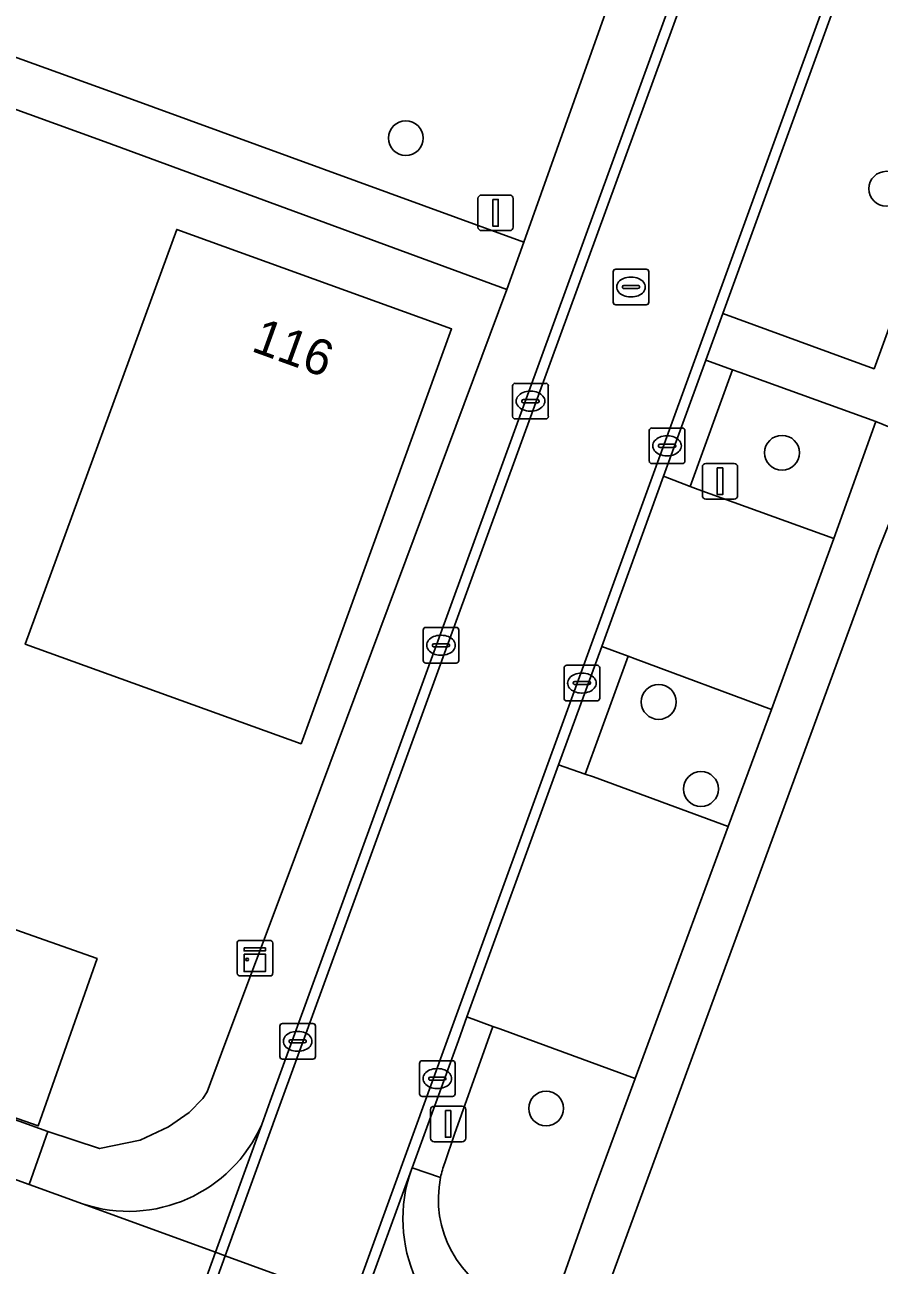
# Model space of a CAD drawing. Extents: x 155275 to 156265, y 382654 to 383635.
# Drawn here: x 155961.56 to 155985.53, y 382876.12 to 382910.94 of the extents above; entities that cross this region are included whole.
import ezdxf

# ---------------------------------------------------------------- set-up
doc = ezdxf.new("R2010")
doc.units = 0
for name, color, linetype in [('IMGEO_Boom', 7, 'Continuous'), ('IMGEO_Erf', 7, 'Continuous'), ('IMGEO_Groenvoorziening', 7, 'Continuous'), ('IMGEO_Kast', 7, 'Continuous'), ('IMGEO_Kolk', 7, 'Continuous'), ('IMGEO_Lichtmast', 7, 'Continuous'), ('IMGEO_Pand', 7, 'Continuous'), ('IMGEO_Pand_nummerreeks', 7, 'Continuous'), ('IMGEO_Parkeervlak_open', 7, 'Continuous'), ('IMGEO_Rijbaan_lokaal_gesloten', 7, 'Continuous'), ('IMGEO_Rijbaan_lokaal_open', 7, 'Continuous'), ('IMGEO_Rioolput', 7, 'Continuous'), ('IMGEO_Voetpad_open', 7, 'Continuous')]:
    doc.layers.add(name, color=color, linetype=linetype)

msp = doc.modelspace()

# ---------------------------------------------------------------- linework, layer by layer
at = {"layer": 'IMGEO_Boom'}
for centre in [(155972.247, 382907.764), (155985.731, 382906.343), (155982.803, 382898.931), (155979.343, 382891.936), (155980.529, 382889.492), (155976.184, 382880.524)]:
    msp.add_circle(centre, 0.489, dxfattribs=at)
at = {"layer": 'IMGEO_Erf'}
for points in [[(155975.085, 382903.519), (155963.808, 382907.656), (155935.757, 382917.844), (155923.739, 382922.208), (155888.788, 382934.902), (155887.843, 382935.242), (155879.927, 382913.581)], [(155882.198, 382908.814), (155888.809, 382906.56), (155914.272, 382897.319), (155926.717, 382892.835), (155943.231, 382886.789), (155948.645, 382884.835), (155950.836, 382890.892), (155956.798, 382888.735), (155954.606, 382882.673), (155954.644, 382882.601), (155962.207, 382879.881), (155963.654, 382879.4), (155964.795, 382879.631), (155965.592, 382880.01), (155966.17, 382880.408), (155966.548, 382880.807), (155966.671, 382880.994), (155967.174, 382882.325), (155968.914, 382886.988), (155975.085, 382903.519)], [(156049.271, 382876.469), (155986.733, 382899.275), (155985.513, 382896.209), (155977.474, 382874.314), (156011.194, 382862.059), (156017.047, 382859.976), (156014.804, 382853.502), (156014.672, 382853.55), (155989.659, 382862.664), (155989.671, 382862.757), (155975.249, 382867.763), (155964.586, 382839.123)]]:
    msp.add_lwpolyline(points, dxfattribs=at)
for points in [[(155965.822, 382905.2), (155973.534, 382902.409), (155969.307, 382890.762), (155961.571, 382893.558)], [(155959.332, 382880.948), (155960.983, 382885.647), (155963.586, 382884.73), (155961.931, 382880.033)]]:
    msp.add_lwpolyline(points, close=True, dxfattribs=at)
at = {"layer": 'IMGEO_Groenvoorziening'}
for points in [[(155978.873, 382914.157), (155957.461, 382921.91), (155954.088, 382912.643), (155964.267, 382908.962), (155975.556, 382904.842)], [(155988.159, 382908.904), (155988.243, 382908.873), (155988.891, 382910.63), (155984.547, 382912.217), (155984.29, 382911.513), (155981.138, 382902.838), (155985.388, 382901.29)], [(155985.435, 382899.805), (155981.631, 382901.186), (155981.414, 382901.263), (155980.223, 382897.987), (155980.451, 382897.9), (155984.256, 382896.523)], [(155982.505, 382891.726), (155978.684, 382893.142), (155978.482, 382893.218), (155977.282, 382889.911), (155977.51, 382889.832), (155981.293, 382888.444)]]:
    msp.add_lwpolyline(points, close=True, dxfattribs=at)
for points in [[(155978.68, 382881.361), (155974.885, 382882.755), (155974.691, 382882.827), (155973.612, 382879.805), (155973.338, 382878.998)], [(155975.121, 382875.129), (155976.275, 382874.707), (155976.958, 382876.636), (155977.473, 382878.089), (155978.68, 382881.361)]]:
    msp.add_lwpolyline(points, dxfattribs=at)
for centre, radius, start, end in [((155976.062, 382878.01), 2.898, 160.0645, 168.4532), ((155976.201, 382877.972), 3.041, 168.2766, 249.2038)]:
    msp.add_arc(centre, radius, start, end, dxfattribs=at)
at = {"layer": 'IMGEO_Kast'}
for p, q in [((155967.59, 382885.243), (155968.431, 382885.243)), ((155968.431, 382885.243), (155967.59, 382885.243)), ((155967.515, 382884.318), (155967.515, 382885.159)), ((155967.515, 382885.159), (155967.515, 382884.318)), ((155968.515, 382885.168), (155968.515, 382884.327)), ((155968.515, 382884.327), (155968.515, 382885.168)), ((155968.44, 382884.243), (155967.599, 382884.243)), ((155967.599, 382884.243), (155968.44, 382884.243))]:
    msp.add_line(p, q, dxfattribs=at)
for points in [[(155967.71, 382885.033), (155968.31, 382885.033), (155968.31, 382884.948), (155967.71, 382884.948), (155967.71, 382885.033)], [(155967.71, 382884.858), (155968.31, 382884.858), (155968.31, 382884.369), (155967.71, 382884.369), (155967.71, 382884.858)]]:
    msp.add_lwpolyline(points, dxfattribs=at)
msp.add_circle((155967.794, 382884.707), 0.0377, dxfattribs=at)
for centre, start, end in [((155967.593, 382885.165), 92.4484, 184.2845), ((155967.593, 382885.165), 92.4484, 184.2845), ((155968.437, 382885.165), 2.4484, 94.2845), ((155968.437, 382885.165), 2.4484, 94.2845), ((155967.593, 382884.321), 182.4484, 274.2845), ((155967.593, 382884.321), 182.4484, 274.2845), ((155968.437, 382884.321), 272.4484, 4.2845), ((155968.437, 382884.321), 272.4484, 4.2845)]:
    msp.add_arc(centre, 0.0779, start, end, dxfattribs=at)
at = {"layer": 'IMGEO_Kolk'}
for p, q in [((155975.245, 382899.954), (155975.245, 382900.806)), ((155975.32, 382900.88), (155976.172, 382900.88)), ((155975.733, 382900.66), (155975.758, 382900.66)), ((155976.246, 382900.806), (155976.246, 382899.954)), ((155975.504, 382900.374), (155975.504, 382900.386)), ((155975.942, 382900.337), (155975.544, 382900.337)), ((155975.547, 382900.423), (155975.945, 382900.423)), ((155975.988, 382900.386), (155975.988, 382900.374)), ((155976.172, 382899.88), (155975.32, 382899.88)), ((155975.756, 382900.1), (155975.731, 382900.1)), ((155979.077, 382898.7), (155979.077, 382899.552)), ((155979.152, 382899.626), (155980.004, 382899.626)), ((155980.078, 382899.552), (155980.078, 382898.7)), ((155979.379, 382899.169), (155979.777, 382899.169)), ((155979.565, 382899.406), (155979.59, 382899.406)), ((155979.336, 382899.12), (155979.336, 382899.132)), ((155979.774, 382899.083), (155979.376, 382899.083)), ((155979.588, 382898.846), (155979.563, 382898.846)), ((155979.82, 382899.132), (155979.82, 382899.12)), ((155980.004, 382898.626), (155979.152, 382898.626)), ((155972.734, 382893.102), (155972.734, 382893.954)), ((155972.809, 382894.028), (155973.661, 382894.028)), ((155973.735, 382893.954), (155973.735, 382893.102)), ((155973.036, 382893.571), (155973.434, 382893.571)), ((155973.222, 382893.808), (155973.247, 382893.808)), ((155972.993, 382893.522), (155972.993, 382893.534)), ((155973.431, 382893.485), (155973.033, 382893.485)), ((155973.245, 382893.248), (155973.22, 382893.248)), ((155973.477, 382893.534), (155973.477, 382893.522)), ((155973.661, 382893.028), (155972.809, 382893.028)), ((155976.688, 382892.039), (155976.688, 382892.891)), ((155976.763, 382892.965), (155977.615, 382892.965)), ((155977.689, 382892.891), (155977.689, 382892.039)), ((155977.176, 382892.745), (155977.201, 382892.745)), ((155976.947, 382892.459), (155976.947, 382892.471)), ((155977.385, 382892.422), (155976.987, 382892.422)), ((155976.99, 382892.508), (155977.388, 382892.508)), ((155977.199, 382892.185), (155977.174, 382892.185)), ((155977.431, 382892.471), (155977.431, 382892.459)), ((155977.615, 382891.965), (155976.763, 382891.965)), ((155968.712, 382881.983), (155968.712, 382882.835)), ((155968.787, 382882.909), (155969.639, 382882.909)), ((155969.713, 382882.835), (155969.713, 382881.983)), ((155969.014, 382882.452), (155969.412, 382882.452)), ((155969.2, 382882.689), (155969.225, 382882.689)), ((155968.971, 382882.403), (155968.971, 382882.415)), ((155969.409, 382882.366), (155969.011, 382882.366)), ((155969.223, 382882.129), (155969.198, 382882.129)), ((155969.455, 382882.415), (155969.455, 382882.403)), ((155969.639, 382881.909), (155968.787, 382881.909)), ((155972.63, 382880.937), (155972.63, 382881.789)), ((155972.705, 382881.863), (155973.557, 382881.863)), ((155973.631, 382881.789), (155973.631, 382880.937)), ((155972.932, 382881.406), (155973.33, 382881.406)), ((155973.118, 382881.643), (155973.143, 382881.643)), ((155972.889, 382881.357), (155972.889, 382881.369)), ((155973.327, 382881.32), (155972.929, 382881.32)), ((155973.141, 382881.083), (155973.116, 382881.083)), ((155973.373, 382881.369), (155973.373, 382881.357)), ((155973.557, 382880.863), (155972.705, 382880.863))]:
    msp.add_line(p, q, dxfattribs=at)
for points in [[(155975.245, 382899.954), (155975.245, 382900.806)], [(155975.32, 382900.88), (155976.172, 382900.88)], [(155976.246, 382900.806), (155976.246, 382899.954)], [(155976.172, 382899.88), (155975.32, 382899.88)], [(155979.077, 382898.7), (155979.077, 382899.552)], [(155979.152, 382899.626), (155980.004, 382899.626)], [(155980.078, 382899.552), (155980.078, 382898.7)], [(155980.004, 382898.626), (155979.152, 382898.626)], [(155972.734, 382893.102), (155972.734, 382893.954)], [(155972.809, 382894.028), (155973.661, 382894.028)], [(155973.735, 382893.954), (155973.735, 382893.102)], [(155973.661, 382893.028), (155972.809, 382893.028)], [(155976.688, 382892.039), (155976.688, 382892.891)], [(155976.763, 382892.965), (155977.615, 382892.965)], [(155977.689, 382892.891), (155977.689, 382892.039)], [(155977.615, 382891.965), (155976.763, 382891.965)], [(155968.712, 382881.983), (155968.712, 382882.835)], [(155968.787, 382882.909), (155969.639, 382882.909)], [(155969.713, 382882.835), (155969.713, 382881.983)], [(155969.639, 382881.909), (155968.787, 382881.909)], [(155972.63, 382880.937), (155972.63, 382881.789)], [(155972.705, 382881.863), (155973.557, 382881.863)], [(155973.631, 382881.789), (155973.631, 382880.937)], [(155973.557, 382880.863), (155972.705, 382880.863)]]:
    msp.add_lwpolyline(points, dxfattribs=at)
for centre, radius, start, end in [((155975.322, 382900.804), 0.0765, 91.552, 178.448), ((155975.322, 382900.804), 0.0765, 91.552, 178.448), ((155976.17, 382900.804), 0.0765, 1.552, 88.448), ((155976.17, 382900.804), 0.0765, 1.552, 88.448), ((155975.544, 382900.383), 0.0403, 85.8775, 175.7526), ((155975.541, 382900.373), 0.0366, 178.938, 274.7102), ((155975.945, 382900.38), 0.043, 264.8664, 352.4533), ((155975.949, 382900.385), 0.0386, 1.7309, 96.639), ((155975.322, 382899.956), 0.0765, 181.552, 268.448), ((155975.322, 382899.956), 0.0765, 181.552, 268.448), ((155976.17, 382899.956), 0.0765, 271.552, 358.448), ((155976.17, 382899.956), 0.0765, 271.552, 358.448), ((155979.154, 382899.55), 0.0765, 91.552, 178.448), ((155979.154, 382899.55), 0.0765, 91.552, 178.448), ((155980.002, 382899.55), 0.0765, 1.552, 88.448), ((155980.002, 382899.55), 0.0765, 1.552, 88.448), ((155979.376, 382899.129), 0.0403, 85.8775, 175.7526), ((155979.781, 382899.131), 0.0386, 1.7309, 96.639), ((155979.373, 382899.119), 0.0366, 178.938, 274.7102), ((155979.777, 382899.126), 0.043, 264.8664, 352.4533), ((155979.154, 382898.702), 0.0765, 181.552, 268.448), ((155979.154, 382898.702), 0.0765, 181.552, 268.448), ((155980.002, 382898.702), 0.0765, 271.552, 358.448), ((155980.002, 382898.702), 0.0765, 271.552, 358.448), ((155972.811, 382893.952), 0.0765, 91.552, 178.448), ((155972.811, 382893.952), 0.0765, 91.552, 178.448), ((155973.659, 382893.952), 0.0765, 1.552, 88.448), ((155973.659, 382893.952), 0.0765, 1.552, 88.448), ((155973.033, 382893.531), 0.0403, 85.8775, 175.7526), ((155973.438, 382893.533), 0.0386, 1.7309, 96.639), ((155973.03, 382893.521), 0.0366, 178.938, 274.7102), ((155973.434, 382893.528), 0.043, 264.8664, 352.4533), ((155972.811, 382893.104), 0.0765, 181.552, 268.448), ((155972.811, 382893.104), 0.0765, 181.552, 268.448), ((155973.659, 382893.104), 0.0765, 271.552, 358.448), ((155973.659, 382893.104), 0.0765, 271.552, 358.448), ((155976.765, 382892.889), 0.0765, 91.552, 178.448), ((155976.765, 382892.889), 0.0765, 91.552, 178.448), ((155977.613, 382892.889), 0.0765, 1.552, 88.448), ((155977.613, 382892.889), 0.0765, 1.552, 88.448), ((155976.987, 382892.468), 0.0403, 85.8775, 175.7526), ((155976.984, 382892.458), 0.0366, 178.938, 274.7102), ((155977.388, 382892.465), 0.043, 264.8664, 352.4533), ((155977.392, 382892.47), 0.0386, 1.7309, 96.639), ((155976.765, 382892.041), 0.0765, 181.552, 268.448), ((155976.765, 382892.041), 0.0765, 181.552, 268.448), ((155977.613, 382892.041), 0.0765, 271.552, 358.448), ((155977.613, 382892.041), 0.0765, 271.552, 358.448), ((155968.789, 382882.833), 0.0765, 91.552, 178.448), ((155968.789, 382882.833), 0.0765, 91.552, 178.448), ((155969.637, 382882.833), 0.0765, 1.552, 88.448), ((155969.637, 382882.833), 0.0765, 1.552, 88.448), ((155969.011, 382882.412), 0.0403, 85.8775, 175.7526), ((155969.416, 382882.414), 0.0386, 1.7309, 96.639), ((155969.008, 382882.402), 0.0366, 178.938, 274.7102), ((155969.412, 382882.409), 0.043, 264.8664, 352.4533), ((155968.789, 382881.985), 0.0765, 181.552, 268.448), ((155968.789, 382881.985), 0.0765, 181.552, 268.448), ((155969.637, 382881.985), 0.0765, 271.552, 358.448), ((155969.637, 382881.985), 0.0765, 271.552, 358.448), ((155972.707, 382881.787), 0.0765, 91.552, 178.448), ((155972.707, 382881.787), 0.0765, 91.552, 178.448), ((155973.555, 382881.787), 0.0765, 1.552, 88.448), ((155973.555, 382881.787), 0.0765, 1.552, 88.448), ((155972.929, 382881.366), 0.0403, 85.8775, 175.7526), ((155973.334, 382881.368), 0.0386, 1.7309, 96.639), ((155972.926, 382881.356), 0.0366, 178.938, 274.7102), ((155973.33, 382881.363), 0.043, 264.8664, 352.4533), ((155972.707, 382880.939), 0.0765, 181.552, 268.448), ((155972.707, 382880.939), 0.0765, 181.552, 268.448), ((155973.555, 382880.939), 0.0765, 271.552, 358.448), ((155973.555, 382880.939), 0.0765, 271.552, 358.448)]:
    msp.add_arc(centre, radius, start, end, dxfattribs=at)
for centre, major_axis, ratio, start_param, end_param in [((155975.732, 382900.38), (-0.387, 0.002), 0.722429, 4.712389, 7.853982), ((155975.757, 382900.38), (-0.39, 0.002), 0.717154, 1.570796, 4.712389), ((155979.564, 382899.126), (-0.387, 0.002), 0.722429, 4.712389, 7.853982), ((155979.589, 382899.126), (-0.39, 0.002), 0.717154, 1.570796, 4.712389), ((155973.221, 382893.528), (-0.387, 0.002), 0.722429, 4.712389, 7.853982), ((155973.246, 382893.528), (-0.39, 0.002), 0.717154, 1.570796, 4.712389), ((155977.175, 382892.465), (-0.387, 0.002), 0.722429, 4.712389, 7.853982), ((155977.2, 382892.465), (-0.39, 0.002), 0.717154, 1.570796, 4.712389), ((155969.199, 382882.409), (-0.387, 0.002), 0.722429, 4.712389, 7.853982), ((155969.224, 382882.409), (-0.39, 0.002), 0.717154, 1.570796, 4.712389), ((155973.117, 382881.363), (-0.387, 0.002), 0.722429, 4.712389, 7.853982), ((155973.142, 382881.363), (-0.39, 0.002), 0.717154, 1.570796, 4.712389)]:
    msp.add_ellipse(centre, major_axis=major_axis, ratio=ratio, start_param=start_param, end_param=end_param, dxfattribs=at)
at = {"layer": 'IMGEO_Lichtmast'}
for p, q in [((155974.372, 382906.166), (155975.162, 382906.166)), ((155975.162, 382906.166), (155974.372, 382906.166)), ((155974.272, 382905.266), (155974.272, 382906.066)), ((155974.272, 382906.066), (155974.272, 382905.266)), ((155975.262, 382906.066), (155975.262, 382905.266)), ((155975.262, 382905.266), (155975.262, 382906.066)), ((155975.162, 382905.166), (155974.372, 382905.166)), ((155974.372, 382905.166), (155975.162, 382905.166)), ((155980.568, 382897.731), (155980.568, 382898.531)), ((155980.568, 382898.531), (155980.568, 382897.731)), ((155980.668, 382898.631), (155981.458, 382898.631)), ((155981.458, 382898.631), (155980.668, 382898.631)), ((155981.558, 382898.531), (155981.558, 382897.731)), ((155981.558, 382897.731), (155981.558, 382898.531)), ((155981.458, 382897.631), (155980.668, 382897.631)), ((155980.668, 382897.631), (155981.458, 382897.631)), ((155972.94, 382879.691), (155972.94, 382880.491)), ((155972.94, 382880.491), (155972.94, 382879.691)), ((155973.04, 382880.591), (155973.83, 382880.591)), ((155973.83, 382880.591), (155973.04, 382880.591)), ((155973.93, 382880.491), (155973.93, 382879.691)), ((155973.93, 382879.691), (155973.93, 382880.491)), ((155973.83, 382879.591), (155973.04, 382879.591)), ((155973.04, 382879.591), (155973.83, 382879.591))]:
    msp.add_line(p, q, dxfattribs=at)
for points in [[(155974.692, 382906.041), (155974.842, 382906.041), (155974.842, 382905.291), (155974.692, 382905.291), (155974.692, 382906.041)], [(155980.988, 382898.506), (155981.138, 382898.506), (155981.138, 382897.756), (155980.988, 382897.756), (155980.988, 382898.506)], [(155973.36, 382880.466), (155973.51, 382880.466), (155973.51, 382879.716), (155973.36, 382879.716), (155973.36, 382880.466)]]:
    msp.add_lwpolyline(points, dxfattribs=at)
for centre, start, end in [((155974.372, 382906.066), 90, 180), ((155974.372, 382906.066), 90, 180), ((155975.162, 382906.066), 0, 90), ((155975.162, 382906.066), 360, 90), ((155974.372, 382905.266), 180, 270), ((155974.372, 382905.266), 180, 270), ((155975.162, 382905.266), 270, 0), ((155975.162, 382905.266), 270, 0), ((155980.668, 382898.531), 90, 180), ((155980.668, 382898.531), 90, 180), ((155981.458, 382898.531), 0, 90), ((155981.458, 382898.531), 360, 90), ((155980.668, 382897.731), 180, 270), ((155980.668, 382897.731), 180, 270), ((155981.458, 382897.731), 270, 0), ((155981.458, 382897.731), 270, 0), ((155973.04, 382880.491), 90, 180), ((155973.04, 382880.491), 90, 180), ((155973.83, 382880.491), 0, 90), ((155973.83, 382880.491), 360, 90), ((155973.04, 382879.691), 180, 270), ((155973.04, 382879.691), 180, 270), ((155973.83, 382879.691), 270, 0), ((155973.83, 382879.691), 270, 0)]:
    msp.add_arc(centre, 0.1, start, end, dxfattribs=at)
at = {"layer": 'IMGEO_Pand'}
for points in [[(155973.534, 382902.409), (155965.822, 382905.2), (155961.571, 382893.558), (155969.307, 382890.762)], [(155959.332, 382880.948), (155961.931, 382880.033), (155963.586, 382884.73), (155960.983, 382885.647)]]:
    msp.add_lwpolyline(points, close=True, dxfattribs=at)
at = {"layer": 'IMGEO_Parkeervlak_open'}
for points in [[(155984.256, 382896.523), (155980.451, 382897.9), (155980.223, 382897.987), (155979.479, 382898.272), (155977.743, 382893.496), (155978.482, 382893.218), (155978.684, 382893.142), (155982.505, 382891.726)], [(155981.293, 382888.444), (155977.51, 382889.832), (155977.282, 382889.911), (155976.535, 382890.17), (155973.964, 382883.095), (155974.691, 382882.827), (155974.885, 382882.755), (155978.68, 382881.361)]]:
    msp.add_lwpolyline(points, close=True, dxfattribs=at)
at = {"layer": 'IMGEO_Rijbaan_lokaal_gesloten'}
for points in [[(155990.869, 382941.386), (155990.616, 382941.478), (155989.298, 382937.8), (155988.716, 382936.177), (155981.583, 382916.812), (155976.023, 382901.548), (155968.442, 382880.729), (155968.205, 382880.073), (155966.906, 382876.487), (155967.181, 382876.387), (155968.713, 382880.618), (155976.296, 382901.446), (155981.859, 382916.715), (155988.961, 382936.106)], [(155967.181, 382876.387), (155966.906, 382876.487), (155965.631, 382872.963), (155965.905, 382872.862)]]:
    msp.add_lwpolyline(points, close=True, dxfattribs=at)
msp.add_lwpolyline([(155984.021, 382911.618), (155973.447, 382882.532), (155970.743, 382875.09), (155971.015, 382874.99), (155972.405, 382878.81), (155972.423, 382878.859), (155973.722, 382882.429), (155973.964, 382883.095), (155976.535, 382890.17), (155977.743, 382893.496), (155979.479, 382898.272), (155980.662, 382901.529), (155981.138, 382902.838), (155984.29, 382911.513)], dxfattribs=at)
at = {"layer": 'IMGEO_Rijbaan_lokaal_open'}
for points in [[(155994.401, 382940.096), (155990.869, 382941.386), (155988.961, 382936.106), (155981.859, 382916.715), (155976.296, 382901.446), (155968.713, 382880.618), (155967.181, 382876.387), (155970.743, 382875.09), (155973.447, 382882.532), (155984.021, 382911.618), (155992.82, 382935.75)], [(155883.262, 382906.894), (155880.59, 382907.807), (155876.928, 382909.197), (155875.66, 382905.722), (155879.327, 382904.418), (155961.883, 382874.346), (155965.631, 382872.963), (155966.906, 382876.487), (155963.18, 382877.844), (155961.679, 382878.39)], [(155970.743, 382875.09), (155967.181, 382876.387), (155965.905, 382872.862), (155969.457, 382871.551)]]:
    msp.add_lwpolyline(points, close=True, dxfattribs=at)
for points in [[(155963.18, 382877.844), (155966.906, 382876.487), (155968.205, 382880.073)], [(155972.405, 382878.81), (155971.015, 382874.99), (155974.767, 382873.624)]]:
    msp.add_lwpolyline(points, dxfattribs=at)
for centre, radius, start, end in [((155964.467, 382881.722), 4.085, 251.64, 336.2024), ((155976.248, 382877.429), 4.083, 160.2394, 248.7351)]:
    msp.add_arc(centre, radius, start, end, dxfattribs=at)
at = {"layer": 'IMGEO_Rioolput'}
for p, q in [((155978.139, 382904.084), (155978.991, 382904.084)), ((155978.064, 382903.158), (155978.064, 382904.01)), ((155978.552, 382903.864), (155978.577, 382903.864)), ((155979.065, 382904.01), (155979.065, 382903.158)), ((155978.323, 382903.578), (155978.323, 382903.59)), ((155978.761, 382903.541), (155978.363, 382903.541)), ((155978.366, 382903.627), (155978.764, 382903.627)), ((155978.807, 382903.59), (155978.807, 382903.578)), ((155978.991, 382903.084), (155978.139, 382903.084)), ((155978.575, 382903.304), (155978.55, 382903.304))]:
    msp.add_line(p, q, dxfattribs=at)
for points in [[(155978.139, 382904.084), (155978.991, 382904.084)], [(155978.064, 382903.158), (155978.064, 382904.01)], [(155979.065, 382904.01), (155979.065, 382903.158)], [(155978.991, 382903.084), (155978.139, 382903.084)]]:
    msp.add_lwpolyline(points, dxfattribs=at)
for centre, radius, start, end in [((155978.141, 382904.008), 0.0765, 91.552, 178.448), ((155978.141, 382904.008), 0.0765, 91.552, 178.448), ((155978.989, 382904.008), 0.0765, 1.552, 88.448), ((155978.989, 382904.008), 0.0765, 1.552, 88.448), ((155978.363, 382903.587), 0.0403, 85.8775, 175.7526), ((155978.36, 382903.577), 0.0366, 178.938, 274.7102), ((155978.764, 382903.584), 0.043, 264.8664, 352.4533), ((155978.768, 382903.589), 0.0386, 1.7309, 96.639), ((155978.141, 382903.16), 0.0765, 181.552, 268.448), ((155978.141, 382903.16), 0.0765, 181.552, 268.448), ((155978.989, 382903.16), 0.0765, 271.552, 358.448), ((155978.989, 382903.16), 0.0765, 271.552, 358.448)]:
    msp.add_arc(centre, radius, start, end, dxfattribs=at)
for centre, major_axis, ratio, start_param, end_param in [((155978.551, 382903.584), (-0.387, 0.002), 0.722429, 4.712389, 7.853982), ((155978.576, 382903.584), (-0.39, 0.002), 0.717154, 1.570796, 4.712389)]:
    msp.add_ellipse(centre, major_axis=major_axis, ratio=ratio, start_param=start_param, end_param=end_param, dxfattribs=at)
at = {"layer": 'IMGEO_Voetpad_open'}
for points in [[(155957.461, 382921.91), (155978.873, 382914.157), (155979.368, 382915.548), (155902.581, 382943.607), (155892.278, 382947.324), (155891.754, 382945.92), (155948.422, 382925.21), (155945.176, 382915.877), (155936.24, 382919.133), (155935.757, 382917.844), (155963.808, 382907.656), (155975.085, 382903.519), (155975.556, 382904.842), (155964.267, 382908.962), (155954.088, 382912.643)], [(155981.414, 382901.263), (155980.662, 382901.529), (155979.479, 382898.272), (155980.223, 382897.987)], [(155978.482, 382893.218), (155977.743, 382893.496), (155976.535, 382890.17), (155977.282, 382889.911)]]:
    msp.add_lwpolyline(points, close=True, dxfattribs=at)
for points in [[(155968.205, 382880.073), (155968.442, 382880.729), (155976.023, 382901.548), (155981.583, 382916.812), (155988.716, 382936.177), (155989.298, 382937.8)], [(155987.536, 382937.682), (155979.368, 382915.548), (155978.873, 382914.157), (155975.556, 382904.842), (155975.085, 382903.519), (155968.914, 382886.988), (155967.174, 382882.325), (155966.671, 382880.994), (155966.548, 382880.807), (155966.17, 382880.408), (155965.592, 382880.01), (155964.795, 382879.631), (155963.654, 382879.4), (155962.207, 382879.881), (155961.679, 382878.39), (155963.18, 382877.844)], [(156030.725, 382896.891), (156005.755, 382906.062), (155991.066, 382911.384), (155989.862, 382911.82), (155986.101, 382913.183), (155985.791, 382913.295), (155985.039, 382913.569), (155984.547, 382912.217), (155988.891, 382910.63), (155988.243, 382908.873), (155988.159, 382908.904), (155985.388, 382901.29), (155981.138, 382902.838), (155980.662, 382901.529), (155981.414, 382901.263), (155981.631, 382901.186), (155985.435, 382899.805), (155986.733, 382899.275), (156049.271, 382876.469)], [(155881.151, 382909.445), (155880.59, 382907.807), (155883.262, 382906.894), (155961.679, 382878.39), (155962.207, 382879.881), (155954.644, 382882.601), (155954.606, 382882.673)], [(155985.513, 382896.209), (155986.733, 382899.275), (155985.435, 382899.805), (155984.256, 382896.523), (155982.505, 382891.726), (155981.293, 382888.444), (155978.68, 382881.361), (155977.473, 382878.089), (155976.958, 382876.636), (155976.275, 382874.707), (155975.121, 382875.129)], [(155974.767, 382873.624), (155976.929, 382872.845), (155977.474, 382874.314), (155985.513, 382896.209)], [(155974.691, 382882.827), (155973.964, 382883.095), (155973.722, 382882.429), (155972.423, 382878.859), (155973.223, 382878.59)], [(155973.338, 382878.998), (155973.612, 382879.805), (155974.691, 382882.827)], [(155973.223, 382878.59), (155972.423, 382878.859), (155972.405, 382878.81)]]:
    msp.add_lwpolyline(points, dxfattribs=at)
for centre, radius, start, end in [((155964.467, 382881.722), 4.085, 251.64, 336.2024), ((155976.062, 382878.01), 2.898, 160.0645, 168.4532), ((155976.248, 382877.429), 4.083, 160.2394, 248.7351), ((155976.201, 382877.972), 3.041, 168.2766, 249.2038)]:
    msp.add_arc(centre, radius, start, end, dxfattribs=at)

# ---------------------------------------------------------------- texts
at = {"layer": 'IMGEO_Pand_nummerreeks'}
msp.add_text('116', height=1, rotation=340.1081, dxfattribs=at).set_placement((155967.878, 382901.797))

doc.saveas('drawing.dxf')
